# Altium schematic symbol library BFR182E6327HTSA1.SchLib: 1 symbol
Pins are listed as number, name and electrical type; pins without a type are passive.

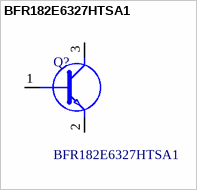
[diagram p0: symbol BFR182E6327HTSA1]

## BFR182E6327HTSA1
designator Q?
RF Bipolar Transistors NPN Silicon RF TRANSISTOR; Manufacturer_Name: Infineon; Geometry.Height: 1.1mm
footprint SOT95P240X110-3N
pins: 1 B, 2 E, 3 C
